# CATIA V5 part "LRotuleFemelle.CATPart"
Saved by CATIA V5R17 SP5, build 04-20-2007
Part number: RotuleFemelle
Publications: "Centre", "Facteur d'échelle"
Bounding box of the stored display mesh (mm): x -4.763 to 4.763, y 0 to 5.5, z -4.755 to 4.755
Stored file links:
  E:\Mes documents\03_Ressources pédagogiques\01_Catia\Buggy Dassault\SchemaCinematiqueFinal\LRotuleFemelle.CATPart
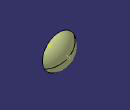
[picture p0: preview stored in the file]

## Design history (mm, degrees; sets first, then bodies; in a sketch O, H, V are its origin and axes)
External parameters (linked from other documents)
  `External.Facteur d'échelle` = 2
AxisSystem1: origin (0, 0, 0), X (1, 0, 0), Y (0, 1, 0), Z (0, 0, 1)
Body1 "RotuleFemelle" (main body)
  Circle1: type CtrRad, Start 90, End 150, Center vertex [YZ plane of AxisSystem1 | ZX plane of AxisSystem1 | XY plane of AxisSystem1], Support XY plane of AxisSystem1, Radius 5.5 {= 2.75mm*`External.Facteur d'échelle`}, FirstDirection (1, 0, 0)
  Revol1: Element1 Circle1, Line edge [YZ plane of AxisSystem1 | XY plane of AxisSystem1], Angle1 180
  Point1 "Centre": type Center, Curve Circle1
  Point2: (0, 0, 0), relative to vertex of Circle1, in AxisSystem1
